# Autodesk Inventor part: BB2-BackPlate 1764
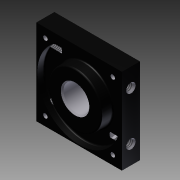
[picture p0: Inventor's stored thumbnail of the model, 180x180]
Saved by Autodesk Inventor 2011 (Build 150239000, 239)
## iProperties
Company: FirstCadLibrary
Shininess: 64.0
Length Units: 11269
Angle Units: 11279
Time Units: 11290
Mass Units: 11283
Length Display Precision: 3
Angle Display Precision: 2
Compacted: True
Part Number: BB2-BackPlate 1764
Document SubType Name: Modeling
Created: 2007-01
Designer: Ed Sparks
Material: Aluminum-6061-AHC
Catalog Web Link: www.banebots.com
Vendor: BaneBots
Mass: 139.924 g
Surface Area: 166.185 cm^2
Volume: 51.6326 cm^3
Density: 2.71 g/cm^3
Density: 0.0
Volumn: 0.0
Area: 0.0
PropertySet Name: Model Information
Control State: 0
Master: False
Checked Out: False
Author: Ed Sparks
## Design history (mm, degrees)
sketch "Sketch1"
  geometry: L1 (-31.75, 31.75)-(31.75, 31.75); L2 (31.75, 31.75)-(31.75, -31.75); L3 (31.75, -31.75)-(-31.75, -31.75); L4 (-31.75, -31.75)-(-31.75, 31.75); L5 (0, 0)-(0, 31.75); L6 (0, 0)-(0, -31.75); L7 (0, 0)-(31.75, 0); L8 (0, 0)-(-31.75, 0)
  constraints: 16 end point, 4 midpoint, 2 collinear, 2 parallel, 1 horizontal, 1 perpendicular, 1 other
  dimensions: "d0" = 63.5 distance of L1.end L2.end; "d1" = 63.5 distance of L1.start L1.end
extrude "Extrusion1" new body sketch "Sketch1" stored distance "d2" = 13.4; taper "d3" = 0 deg
sketch "Sketch2"
  geometry: C1 r 31 at (0, 0)
  constraints: 1 centre point
  dimensions: "d4" = 62 diameter of C1
extrude "Extrusion2" cut sketch "Sketch2" distance "d5" = 5; taper "d6" = 0 deg
sketch "Sketch3"
  geometry: C1 r 20 at (-0.807, 0)
  constraints: 1 centre point
  dimensions: "d7" = 40 diameter of C1
extrude "Extrusion3" join sketch "Sketch3" distance "d8" = 8; taper "d9" = 0 deg
fillet "Fillet1" dims "d10" = 1
sketch "Sketch6"
  geometry: C1 r 25 at (0, 0)
  constraints: 1 centre point
  dimensions: "d13" = 50 diameter of C1
extrude "Extrusion4" join sketch "Sketch6" distance "d14" = 6; taper "d15" = 0 deg
sketch "Sketch7"
  geometry: C1 r 25 at (0, 0) reference; 1 further point
  dimensions: "d16" = 25 horizontal distance of point (-25, 25) C1.centre; "d17" = 25 horizontal distance of C1.centre point (-25, 25)
hole "Hole1" sketch "Sketch7" at (-25, 25) diameter "d18" = 3.2; stored, may be unused: countersink angle "d22" = 82 deg, drill point angle "d24" = 118 deg; dims "d19" = 6, "d20" = 6.3, "d21" = 10.3, "d23" = 8
pattern_circular "Circular Pattern1" dims angle "d27" = 360 deg
sketch "Sketch8"
  geometry: C1 r 25 at (0, 0) reference; 1 further point
  constraints: 1 coincident
hole "Hole2" sketch "Sketch8" at (0, 0) diameter "d28" = 19.2; stored, may be unused: countersink angle "d32" = 82 deg, drill point angle "d34" = 118 deg; dims "d29" = 6, "d30" = 6.3, "d31" = 10.3, "d33" = 8
chamfer "Chamfer1" distance "d35" = 1; stored, may be unused: second distance "d36" = 2, angle "d59" = 45 deg
sketch "Sketch9"
  geometry: L1 (63.5, 0)-(0, 0) reference; L2 (0, 0)-(0, -13.4) reference; L3 (0, -13.4)-(63.5, -13.4) reference; L4 (63.5, 0)-(63.5, -13.4) reference; L5 (0, -6.7)-(63.5, -6.7); L6 (31.75, 0)-(31.75, -13.4); 1 further point
  constraints: 4 end point, 4 midpoint, 1 point on line
  dimensions: "d37" = 18 distance from line of point (13.75, -6.7) L6
hole "Hole3" sketch "Sketch9" at (13.75, -6.7) diameter "d38" = 4.978; stored, may be unused: countersink angle "d42" = 82 deg, drill point angle "d44" = 118 deg; dims "d39" = 12, "d40" = 6.3, "d41" = 10.3, "d43" = 13.7
mirror "Mirror1"
mirror "Mirror2"
chamfer "Chamfer2" distance "d45" = 1; stored, may be unused: second distance "d46" = 2, angle "d60" = 45 deg
workplane "Work Plane1"
sketch "Sketch10"
  geometry: L1 (-31.75, -6.7)-(31.75, -6.7) reference; L2 (0, -6.7)-(0, -22.916); 1 further point
  constraints: 2 end point, 1 midpoint, 1 perpendicular, 1 point on line
  dimensions: "d48" = 3.5 distance from line of point (0, -10.2) L1
hole "Hole4" sketch "Sketch10" at (0, -10.2) diameter "d49" = 2.459; stored, may be unused: countersink angle "d53" = 82 deg, drill point angle "d55" = 118 deg; dims "d50" = 6, "d51" = 6.3, "d52" = 10.3, "d54" = 7.5
pattern_circular "Circular Pattern2" dims angle "d58" = 360 deg
body "Solid1"
other parameters: "d47" = 25
